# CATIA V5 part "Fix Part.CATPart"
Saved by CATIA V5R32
Part number: Part4
Bounding box of the stored display mesh (mm): x -100 to 100, y -30 to 50, z -10 to 111
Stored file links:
  D:\PROJECTS\Project 2022\CATIA V5 6R 2022\Resources\Part Files\c16_catia_v5_6r2022_prt\Rack Joint-(Fig16-57)\Fix Part.CATPart
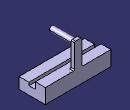
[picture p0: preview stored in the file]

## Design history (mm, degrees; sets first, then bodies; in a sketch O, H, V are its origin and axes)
Body1 (main body)
  Sketch1 on yz-plane, origin (0, 0, 0), H (0, 1, 0), V (0, 0, 1)
    line L1 (50, 35) -> (50, -10)
    line L2 (50, -10) -> (-30, -10)
    line L3 (0, 15) -> (20, 15)
    line L4 (20, 15) -> (20, 35)
    point P5 (0, 15)
    reference intersected line E1 through (0, 0) direction (-1, 0) from xy-plane
    reference intersected line E3 through (0, 0) direction (0, 1) from zx-plane
    line L5 (20, 35) -> (50, 35)
    reference intersected line E4 through (0, 0) direction (-1, 0) from xy-plane
    reference intersected line E6 through (0, 0) direction (0, 1) from zx-plane
    line L6 (0, 15) -> (0, 24)
    line L7 (0, 24) -> (-30, 24)
    line L8 (-30, 24) -> (-30, -10)
    distance H L2 = 10
    distance V L1 = 50
    distance E1 L3 = 15
    length L6 = 9
    length L4 = 20
    length L3 = 20
    length L2 = 80
    vertical: L1 V, L4 V, E3 V, E6 V, L6 V, L8 V
    horizontal: L2 H, L3 H, E1 H, L5 H, E4 H, L7 H
    perpendicularity: E1 L1
    coincidence: P5 V
  Pad1: profile Sketch1, direction (1, 0, 0), length 100, mirrored extent
  Sketch2 on face of Pad1 from Sketch1.L1, origin (0, 50, 0), H (-1, 0, 0), V (0, 0, 1)
    circle A1 centre (0, 100) radius 7.5
    point P1 (0, 100)
    radius A1 = 7.5
    distance H P1 = 100
    coincidence: P1 V
  Pad2: profile Sketch2, direction (0, -1, 0), up to face of Pad1 from Sketch1.L8
  Sketch3 on face of Pad1 from Sketch1.L1, origin (0, 50, 0), H (-1, 0, 0), V (0, 0, 1)
    line L1 (-11, 111) -> (11, 111)
    line L2 (11, 111) -> (11, -10)
    line L3 (11, -10) -> (-11, -10)
    line L4 (-11, -10) -> (-11, 111)
    length L3 = 22
    distance V L2 = 11
    distance L1 L3 = 121
    distance L3 H = 10
    horizontal: L1 H, L3 H
    vertical: L2 V, L4 V
  Pad3: profile Sketch3, direction (0, -1, 0), length 10
  Fillet1: radius 3, on edge [end face of Pad3 | face of Pad1 from Sketch1.L5]; edge [face of Pad3 from Sketch3.L4 | face of Pad1 from Sketch1.L5]; edge [face of Pad1 from Sketch1.L5 | face of Pad3 from Sketch3.L2]; edge [face of Pad2 from Sketch2.A1 | end face of Pad3]; edge [face of Pad3 from Sketch3.L1 | face of Pad3 from Sketch3.L4]; edge [face of Pad3 from Sketch3.L2 | face of Pad3 from Sketch3.L1]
